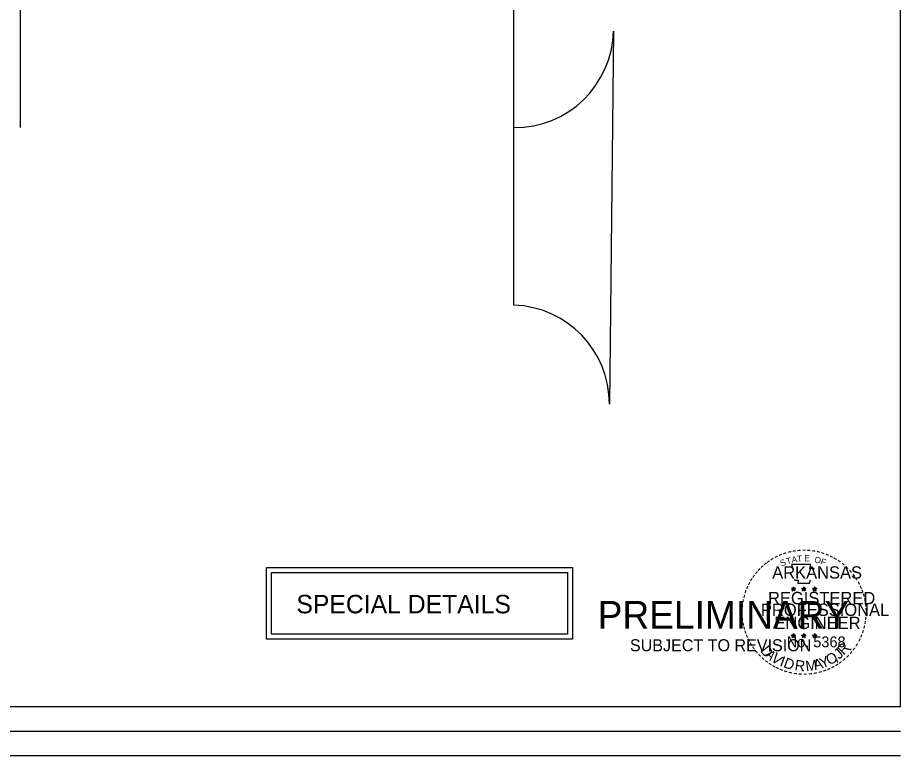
# Model space of a CAD drawing. Extents: x 1944905 to 1956777, y 763871 to 764977.
# Drawn here: x 1950934 to 1951650, y 763871 to 764469 of the extents above; entities that cross this region are included whole.
import ezdxf

# ---------------------------------------------------------------- set-up
doc = ezdxf.new("R2010")
doc.units = 0
for name, color, linetype in [('Default', 7, 'Continuous'), ('R_Border PE', 7, 'Continuous'), ('R_Drive', 7, 'Continuous'), ('R_Horz Alg Annot', 7, 'Continuous')]:
    doc.layers.add(name, color=color, linetype=linetype)

msp = doc.modelspace()

# ---------------------------------------------------------------- linework, layer by layer
at = {"layer": 'Default'}
for p, q in [((1951649.9, 763910.07), (1951649.9, 764937.29)), ((1951649.9, 763910.07), (1950069, 763910.07)), ((1950036.16, 763890.36), (1951649.9, 763890.36)), ((1950036.16, 763870.67), (1951649.9, 763870.67))]:
    msp.add_line(p, q, dxfattribs=at)
for points in [[(1951136, 764022.9), (1951384.01, 764022.9), (1951384.01, 763964.87), (1951136, 763964.87)], [(1951140, 764018.9), (1951380.01, 764018.9), (1951380.01, 763968.87), (1951140, 763968.87)]]:
    msp.add_lwpolyline(points, close=True, dxfattribs=at)
at = {"layer": 'R_Border PE'}
for p, q in [((1951561.56, 764006.04), (1951563.26, 764005.49)), ((1951561.56, 764006.04), (1951562.81, 764005.89)), ((1951561.56, 764006.04), (1951562.81, 764005.84)), ((1951561.56, 764006.04), (1951562.76, 764005.74)), ((1951561.56, 764006.04), (1951562.76, 764005.54)), ((1951561.56, 764006.04), (1951562.71, 764005.44)), ((1951561.56, 764006.04), (1951562.71, 764005.34)), ((1951563.26, 764007.29), (1951563.01, 764006.09)), ((1951563.26, 764007.29), (1951563.06, 764006.04)), ((1951563.26, 764007.29), (1951563.21, 764006.04)), ((1951563.26, 764005.49), (1951563.26, 764007.29)), ((1951563.26, 764007.29), (1951563.61, 764006.04)), ((1951563.26, 764007.29), (1951563.51, 764006.04)), ((1951563.26, 764007.29), (1951563.41, 764006.09)), ((1951565.01, 764006.04), (1951563.26, 764005.49)), ((1951565.01, 764006.04), (1951563.51, 764005.94)), ((1951565.01, 764006.04), (1951563.61, 764005.79)), ((1951565.01, 764006.04), (1951563.61, 764005.69)), ((1951565.01, 764006.04), (1951563.91, 764005.59)), ((1951565.01, 764006.04), (1951564.01, 764005.54)), ((1951565.01, 764006.04), (1951564.06, 764005.49)), ((1951569.86, 764006.04), (1951571.61, 764005.49)), ((1951569.86, 764006.04), (1951571.16, 764005.89)), ((1951569.86, 764006.04), (1951571.16, 764005.84)), ((1951569.86, 764006.04), (1951571.11, 764005.74)), ((1951569.86, 764006.04), (1951571.11, 764005.54)), ((1951569.86, 764006.04), (1951571.06, 764005.44)), ((1951569.86, 764006.04), (1951571.06, 764005.34)), ((1951571.61, 764007.29), (1951571.36, 764006.09)), ((1951571.61, 764007.29), (1951571.41, 764006.04)), ((1951571.61, 764007.29), (1951571.56, 764006.04)), ((1951571.61, 764005.49), (1951571.61, 764007.29)), ((1951571.61, 764007.29), (1951571.96, 764006.04)), ((1951571.61, 764007.29), (1951571.86, 764006.04)), ((1951571.61, 764007.29), (1951571.76, 764006.09)), ((1951573.36, 764006.04), (1951571.61, 764005.49)), ((1951573.36, 764006.04), (1951571.81, 764005.94)), ((1951573.36, 764006.04), (1951571.91, 764005.79)), ((1951573.36, 764006.04), (1951571.91, 764005.69)), ((1951573.36, 764006.04), (1951572.26, 764005.59)), ((1951573.36, 764006.04), (1951572.36, 764005.54)), ((1951573.36, 764006.04), (1951572.41, 764005.49)), ((1951578.71, 764005.99), (1951580.46, 764005.44)), ((1951578.71, 764005.99), (1951580.01, 764005.84)), ((1951578.71, 764005.99), (1951580.01, 764005.74)), ((1951578.71, 764005.99), (1951579.96, 764005.64)), ((1951578.71, 764005.99), (1951579.91, 764005.49)), ((1951578.71, 764005.99), (1951579.91, 764005.39)), ((1951578.71, 764005.99), (1951579.91, 764005.29)), ((1951580.46, 764007.24), (1951580.16, 764006.04)), ((1951580.46, 764007.24), (1951580.26, 764005.99)), ((1951580.46, 764007.24), (1951580.36, 764005.99)), ((1951580.46, 764005.44), (1951580.46, 764007.24)), ((1951580.46, 764007.24), (1951580.81, 764005.99)), ((1951580.46, 764007.24), (1951580.71, 764005.99)), ((1951580.46, 764007.24), (1951580.56, 764006.04)), ((1951582.21, 764005.99), (1951580.46, 764005.44)), ((1951582.21, 764005.99), (1951580.66, 764005.89)), ((1951582.21, 764005.99), (1951580.76, 764005.74)), ((1951582.21, 764005.99), (1951580.76, 764005.64)), ((1951582.21, 764005.99), (1951581.11, 764005.54)), ((1951582.21, 764005.99), (1951581.16, 764005.49)), ((1951582.21, 764005.99), (1951581.26, 764005.44)), ((1951562.21, 764003.99), (1951563.26, 764005.49)), ((1951562.21, 764003.99), (1951562.76, 764005.39)), ((1951562.21, 764003.99), (1951562.81, 764005.24)), ((1951562.21, 764003.99), (1951562.91, 764005.19)), ((1951562.21, 764003.99), (1951563.26, 764005.09)), ((1951562.21, 764003.99), (1951563.06, 764005.04)), ((1951562.21, 764003.99), (1951563.31, 764004.94)), ((1951564.36, 764003.99), (1951563.26, 764005.49)), ((1951564.36, 764003.99), (1951563.26, 764005.09)), ((1951564.36, 764003.99), (1951563.26, 764004.94)), ((1951564.36, 764003.99), (1951563.46, 764005.04)), ((1951564.36, 764003.99), (1951563.61, 764005.24)), ((1951564.36, 764003.99), (1951563.66, 764005.44)), ((1951564.36, 764003.99), (1951563.76, 764005.44)), ((1951570.56, 764003.99), (1951571.61, 764005.49)), ((1951570.56, 764003.99), (1951571.11, 764005.39)), ((1951570.56, 764003.99), (1951571.16, 764005.24)), ((1951570.56, 764003.99), (1951571.26, 764005.19)), ((1951570.56, 764003.99), (1951571.61, 764005.09)), ((1951570.56, 764003.99), (1951571.41, 764005.04)), ((1951570.56, 764003.99), (1951571.66, 764004.94)), ((1951572.71, 764003.99), (1951571.61, 764005.49)), ((1951572.71, 764003.99), (1951571.61, 764005.09)), ((1951572.71, 764003.99), (1951571.61, 764004.94)), ((1951572.71, 764003.99), (1951571.81, 764005.04)), ((1951572.71, 764003.99), (1951571.96, 764005.24)), ((1951572.71, 764003.99), (1951572.01, 764005.44)), ((1951572.71, 764003.99), (1951572.11, 764005.44)), ((1951579.41, 764003.94), (1951580.46, 764005.44)), ((1951579.41, 764003.94), (1951579.96, 764005.34)), ((1951579.41, 764003.94), (1951580.01, 764005.14)), ((1951579.41, 764003.94), (1951580.11, 764005.14)), ((1951579.41, 764003.94), (1951580.46, 764005.04)), ((1951579.41, 764003.94), (1951580.26, 764004.99)), ((1951579.41, 764003.94), (1951580.51, 764004.89)), ((1951581.51, 764003.94), (1951580.46, 764005.44)), ((1951581.51, 764003.94), (1951580.46, 764005.04)), ((1951581.51, 764003.94), (1951580.46, 764004.89)), ((1951581.51, 764003.94), (1951580.66, 764004.99)), ((1951581.51, 764003.94), (1951580.81, 764005.19)), ((1951581.51, 764003.94), (1951580.86, 764005.39)), ((1951581.51, 764003.94), (1951580.96, 764005.39)), ((1951561.51, 763968.19), (1951563.26, 763967.64)), ((1951561.51, 763968.19), (1951562.81, 763968.04)), ((1951561.51, 763968.19), (1951562.81, 763967.94)), ((1951561.51, 763968.19), (1951562.76, 763967.84)), ((1951561.51, 763968.19), (1951562.71, 763967.69)), ((1951561.51, 763968.19), (1951562.71, 763967.59)), ((1951561.51, 763968.19), (1951562.71, 763967.44)), ((1951562.21, 763966.14), (1951563.26, 763967.64)), ((1951562.21, 763966.14), (1951562.76, 763967.54)), ((1951562.21, 763966.14), (1951562.81, 763967.34)), ((1951562.21, 763966.14), (1951562.91, 763967.29)), ((1951562.21, 763966.14), (1951563.26, 763967.24)), ((1951562.21, 763966.14), (1951563.06, 763967.19)), ((1951562.21, 763966.14), (1951563.31, 763967.09)), ((1951563.26, 763969.44), (1951562.96, 763968.24)), ((1951563.26, 763969.44), (1951563.06, 763968.19)), ((1951563.26, 763969.44), (1951563.16, 763968.19)), ((1951563.26, 763967.64), (1951563.26, 763969.44)), ((1951563.26, 763969.44), (1951563.61, 763968.19)), ((1951563.26, 763969.44), (1951563.51, 763968.19)), ((1951563.26, 763969.44), (1951563.36, 763968.19)), ((1951565.01, 763968.19), (1951563.26, 763967.64)), ((1951564.31, 763966.14), (1951563.26, 763967.64)), ((1951564.31, 763966.14), (1951563.26, 763967.19)), ((1951564.31, 763966.14), (1951563.26, 763967.09)), ((1951565.01, 763968.19), (1951563.46, 763968.09)), ((1951564.31, 763966.14), (1951563.46, 763967.19)), ((1951565.01, 763968.19), (1951563.56, 763967.94)), ((1951565.01, 763968.19), (1951563.56, 763967.84)), ((1951564.31, 763966.14), (1951563.61, 763967.34)), ((1951564.31, 763966.14), (1951563.66, 763967.59)), ((1951564.31, 763966.14), (1951563.76, 763967.59)), ((1951565.01, 763968.19), (1951563.91, 763967.74)), ((1951565.01, 763968.19), (1951563.96, 763967.69)), ((1951565.01, 763968.19), (1951564.06, 763967.59)), ((1951569.86, 763968.19), (1951571.61, 763967.64)), ((1951569.86, 763968.19), (1951571.16, 763968.04)), ((1951569.86, 763968.19), (1951571.11, 763967.94)), ((1951569.86, 763968.19), (1951571.11, 763967.84)), ((1951569.86, 763968.19), (1951571.06, 763967.69)), ((1951569.86, 763968.19), (1951571.06, 763967.59)), ((1951569.86, 763968.19), (1951571.06, 763967.44)), ((1951570.51, 763966.14), (1951571.61, 763967.64)), ((1951570.51, 763966.14), (1951571.11, 763967.54)), ((1951570.51, 763966.14), (1951571.16, 763967.34)), ((1951570.51, 763966.14), (1951571.26, 763967.29)), ((1951570.51, 763966.14), (1951571.61, 763967.24)), ((1951570.51, 763966.14), (1951571.41, 763967.19)), ((1951570.51, 763966.14), (1951571.61, 763967.09)), ((1951571.61, 763969.44), (1951571.31, 763968.24)), ((1951571.61, 763969.44), (1951571.41, 763968.19)), ((1951571.61, 763969.44), (1951571.51, 763968.19)), ((1951571.61, 763967.64), (1951571.61, 763969.44)), ((1951571.61, 763969.44), (1951571.96, 763968.19)), ((1951571.61, 763969.44), (1951571.86, 763968.19)), ((1951571.61, 763969.44), (1951571.71, 763968.19)), ((1951573.36, 763968.19), (1951571.61, 763967.64)), ((1951572.66, 763966.14), (1951571.61, 763967.64)), ((1951572.66, 763966.14), (1951571.61, 763967.19)), ((1951572.66, 763966.14), (1951571.61, 763967.09)), ((1951573.36, 763968.19), (1951571.81, 763968.09)), ((1951572.66, 763966.14), (1951571.81, 763967.19)), ((1951573.36, 763968.19), (1951571.91, 763967.94)), ((1951573.36, 763968.19), (1951571.91, 763967.84)), ((1951572.66, 763966.14), (1951571.96, 763967.34)), ((1951572.66, 763966.14), (1951572.01, 763967.59)), ((1951572.66, 763966.14), (1951572.11, 763967.59)), ((1951573.36, 763968.19), (1951572.21, 763967.74)), ((1951573.36, 763968.19), (1951572.31, 763967.69)), ((1951573.36, 763968.19), (1951572.41, 763967.59)), ((1951578.71, 763968.14), (1951580.46, 763967.54)), ((1951578.71, 763968.14), (1951579.96, 763967.99)), ((1951578.71, 763968.14), (1951579.96, 763967.89)), ((1951578.71, 763968.14), (1951579.91, 763967.79)), ((1951578.71, 763968.14), (1951579.91, 763967.64)), ((1951578.71, 763968.14), (1951579.86, 763967.49)), ((1951578.71, 763968.14), (1951579.86, 763967.39)), ((1951579.36, 763966.09), (1951580.46, 763967.54)), ((1951579.36, 763966.09), (1951579.91, 763967.44)), ((1951579.36, 763966.09), (1951580.01, 763967.29)), ((1951579.36, 763966.09), (1951580.11, 763967.24)), ((1951579.36, 763966.09), (1951580.26, 763967.14)), ((1951579.36, 763966.09), (1951580.41, 763967.14)), ((1951579.36, 763966.09), (1951580.46, 763967.04)), ((1951580.46, 763969.39), (1951580.16, 763968.14)), ((1951580.46, 763969.39), (1951580.26, 763968.14)), ((1951580.46, 763969.39), (1951580.36, 763968.14)), ((1951581.51, 763966.09), (1951580.41, 763967.14)), ((1951581.51, 763966.09), (1951580.41, 763966.99)), ((1951580.46, 763967.54), (1951580.46, 763969.39)), ((1951580.46, 763969.39), (1951580.76, 763968.14)), ((1951580.46, 763969.39), (1951580.71, 763968.14)), ((1951580.46, 763969.39), (1951580.56, 763968.14)), ((1951582.16, 763968.14), (1951580.46, 763967.54)), ((1951581.51, 763966.09), (1951580.46, 763967.54)), ((1951581.51, 763966.09), (1951580.61, 763967.14)), ((1951582.16, 763968.14), (1951580.66, 763967.99)), ((1951582.16, 763968.14), (1951580.76, 763967.89)), ((1951582.16, 763968.14), (1951580.76, 763967.79)), ((1951581.51, 763966.09), (1951580.81, 763967.54)), ((1951581.51, 763966.09), (1951580.81, 763967.29)), ((1951581.51, 763966.09), (1951580.96, 763967.54)), ((1951582.16, 763968.14), (1951581.06, 763967.64)), ((1951582.16, 763968.14), (1951581.16, 763967.59)), ((1951582.16, 763968.14), (1951581.21, 763967.54))]:
    msp.add_line(p, q, dxfattribs=at)
for points in [[(1951561.76, 764025.44), (1951563.11, 764021.29)], [(1951579.31, 764020.84), (1951580.01, 764022.24), (1951576.56, 764022.14), (1951577.31, 764025.44), (1951561.76, 764025.44)], [(1951564.21, 764013.34), (1951564.21, 764012.89), (1951567.01, 764012.79), (1951566.76, 764010.44), (1951576.11, 764010.44), (1951577.11, 764013.09)], [(1951563.26, 764007.29), (1951564.36, 764003.99), (1951561.56, 764006.04), (1951565.01, 764006.04), (1951562.21, 764003.99), (1951563.26, 764007.29)], [(1951571.61, 764007.29), (1951572.71, 764003.99), (1951569.86, 764006.04), (1951573.36, 764006.04), (1951570.56, 764003.99), (1951571.61, 764007.29)], [(1951580.46, 764007.24), (1951581.51, 764003.94), (1951578.71, 764005.99), (1951582.21, 764005.99), (1951579.41, 764003.94), (1951580.46, 764007.24)], [(1951563.26, 763969.44), (1951564.31, 763966.14), (1951561.51, 763968.19), (1951565.01, 763968.19), (1951562.21, 763966.14), (1951563.26, 763969.44)], [(1951571.61, 763969.44), (1951572.66, 763966.14), (1951569.86, 763968.19), (1951573.36, 763968.19), (1951570.51, 763966.14), (1951571.61, 763969.44)], [(1951580.46, 763969.39), (1951581.51, 763966.09), (1951578.71, 763968.14), (1951582.16, 763968.14), (1951579.36, 763966.09), (1951580.46, 763969.39)]]:
    msp.add_lwpolyline(points, dxfattribs=at)
for centre, radius in [((1951563.27, 764005.49), 0.861), ((1951563.27, 764005.49), 0.78), ((1951563.27, 764005.49), 0.723), ((1951563.27, 764005.49), 0.664), ((1951563.27, 764005.49), 0.579), ((1951563.27, 764005.49), 0.537), ((1951563.27, 764005.49), 0.495), ((1951571.61, 764005.49), 0.861), ((1951571.61, 764005.49), 0.78), ((1951571.61, 764005.49), 0.723), ((1951571.61, 764005.49), 0.664), ((1951571.61, 764005.49), 0.579), ((1951571.61, 764005.49), 0.537), ((1951571.61, 764005.49), 0.495), ((1951580.45, 764005.43), 0.861), ((1951580.45, 764005.43), 0.78), ((1951580.45, 764005.43), 0.723), ((1951580.45, 764005.43), 0.664), ((1951580.45, 764005.43), 0.579), ((1951563.27, 764005.49), 0.426), ((1951563.27, 764005.49), 0.374), ((1951563.27, 764005.49), 0.311), ((1951563.27, 764005.49), 0.248), ((1951563.27, 764005.49), 0.185), ((1951563.27, 764005.49), 0.148), ((1951563.27, 764005.49), 0.0721), ((1951571.61, 764005.49), 0.426), ((1951571.61, 764005.49), 0.374), ((1951571.61, 764005.49), 0.311), ((1951571.61, 764005.49), 0.248), ((1951571.61, 764005.49), 0.185), ((1951571.61, 764005.49), 0.148), ((1951571.61, 764005.49), 0.0721), ((1951580.45, 764005.43), 0.537), ((1951580.45, 764005.43), 0.495), ((1951580.45, 764005.43), 0.426), ((1951580.45, 764005.43), 0.374), ((1951580.45, 764005.43), 0.311), ((1951580.45, 764005.43), 0.248), ((1951580.45, 764005.43), 0.185), ((1951580.45, 764005.43), 0.148), ((1951580.45, 764005.43), 0.0721), ((1951563.25, 763967.63), 0.861), ((1951563.25, 763967.63), 0.78), ((1951563.25, 763967.63), 0.723), ((1951563.25, 763967.63), 0.664), ((1951563.25, 763967.63), 0.579), ((1951563.25, 763967.63), 0.537), ((1951563.25, 763967.63), 0.495), ((1951563.25, 763967.63), 0.426), ((1951563.25, 763967.63), 0.374), ((1951563.25, 763967.63), 0.311), ((1951563.25, 763967.63), 0.248), ((1951563.25, 763967.63), 0.185), ((1951563.25, 763967.63), 0.148), ((1951563.25, 763967.63), 0.0721), ((1951571.59, 763967.63), 0.861), ((1951571.59, 763967.63), 0.78), ((1951571.59, 763967.63), 0.723), ((1951571.59, 763967.63), 0.664), ((1951571.59, 763967.63), 0.579), ((1951571.59, 763967.63), 0.537), ((1951571.59, 763967.63), 0.495), ((1951571.59, 763967.63), 0.426), ((1951571.59, 763967.63), 0.374), ((1951571.59, 763967.63), 0.311), ((1951571.59, 763967.63), 0.248), ((1951571.59, 763967.63), 0.185), ((1951571.59, 763967.63), 0.148), ((1951571.59, 763967.63), 0.0721), ((1951580.43, 763967.57), 0.861), ((1951580.43, 763967.57), 0.78), ((1951580.43, 763967.57), 0.723), ((1951580.43, 763967.57), 0.664), ((1951580.43, 763967.57), 0.579), ((1951580.43, 763967.57), 0.537), ((1951580.43, 763967.57), 0.495), ((1951580.43, 763967.57), 0.426), ((1951580.43, 763967.57), 0.374), ((1951580.43, 763967.57), 0.311), ((1951580.43, 763967.57), 0.248), ((1951580.43, 763967.57), 0.185), ((1951580.43, 763967.57), 0.148), ((1951580.43, 763967.57), 0.0721)]:
    msp.add_circle(centre, radius, dxfattribs=at)
at = {"layer": 'R_Drive'}
for p, q in [((1951417.27, 764457.94), (1951413.99, 764155.56)), ((1951336.5, 764235.83), (1951336.5, 764379.83))]:
    msp.add_line(p, q, dxfattribs=at)
for centre, start, end in [((1951337.29, 764459.82), 269.43122, 358.65108), ((1951333.99, 764155.87), 359.77958, 88.20531)]:
    msp.add_arc(centre, 80, start, end, dxfattribs=at)
at = {"layer": 'R_Horz Alg Annot'}
for points in [[(1950936.5, 764379.83), (1950936.5, 764731.83)], [(1951336.5, 764379.83), (1951336.5, 764731.83)]]:
    msp.add_lwpolyline(points, dxfattribs=at)

# ---------------------------------------------------------------- texts
at = {"layer": 'Default'}
for s, height, p in [('SPECIAL DETAILS', 15, (1951160.19, 763985.86)), ('PRELIMINARY', 22.5, (1951404.5, 763973.37)), ('        SUBJECT TO REVISION', 9.75, (1951401.68, 763955.1))]:
    msp.add_text(s, height=height, dxfattribs=at).set_placement(p)
at = {"layer": 'R_Border PE'}
for s, height, rotation, p in [('-', 8, 19.17608, (1951555.46, 764031.09)), ('-', 8, 13.63015, (1951559.21, 764032.29)), ('-', 8, 10.21935, (1951562.61, 764033.09)), ('-', 8, 5.89682, (1951566.26, 764033.64)), ('-', 8, 0.18623, (1951570.11, 764033.99)), ('-', 8, 357.74304, (1951573.76, 764033.94)), ('-', 8, 352.16173, (1951577.46, 764033.64)), ('-', 8, 347.20489, (1951581.06, 764033.09)), ('-', 8, 342.3362, (1951584.21, 764032.29)), ('-', 8, 36.23174, (1951543.26, 764024.29)), ('-', 8, 34.06357, (1951546.16, 764026.29)), ('-', 8, 28.79182, (1951549.16, 764028.14)), ('-', 8, 24.30721, (1951552.31, 764029.74)), ('S', 5, 21.59401, (1951553.51, 764023.84)), ('T', 5, 16.4036, (1951558.11, 764025.49)), ('A', 5, 11.21318, (1951562.21, 764026.74)), ('T', 5, 6.02276, (1951566.46, 764027.54)), ('E', 5, 0.83234, (1951572.01, 764028.09)), ('O', 5, 350.4515, (1951580.01, 764027.04)), ('F', 5, 340.07066, (1951584.76, 764025.94)), ('-', 8, 337.85509, (1951587.91, 764031.19)), ('-', 8, 334.12109, (1951591.06, 764029.84)), ('-', 8, 329.64089, (1951593.96, 764028.44)), ('-', 8, 325.86266, (1951597.16, 764026.59)), ('-', 8, 48.42305, (1951536.51, 764017.94)), ('-', 8, 42.96224, (1951538.71, 764020.34)), ('-', 8, 38.95066, (1951540.91, 764022.44)), ('-', 8, 320.52971, (1951600.21, 764024.49)), ('-', 8, 315.57859, (1951603.21, 764022.04)), ('-', 8, 309.87973, (1951606.06, 764019.29)), ('-', 8, 58.07063, (1951530.76, 764010.04)), ('-', 8, 54.23247, (1951532.41, 764012.69)), ('-', 8, 50.61417, (1951534.46, 764015.54)), ('-', 8, 306.65218, (1951608.71, 764016.29)), ('-', 7, 303.67529, (1951611.11, 764013.44)), ('-', 8, 67.77427, (1951527.91, 764003.94)), ('-', 8, 62.87135, (1951529.21, 764006.99)), ('-', 8, 299.66835, (1951612.71, 764010.39)), ('-', 8, 294.66279, (1951614.31, 764007.34)), ('-', 8, 75.46096, (1951525.86, 763997.19)), ('-', 8, 72.39447, (1951526.81, 764000.79)), ('-', 8, 290.57283, (1951615.61, 764004.44)), ('-', 8, 285.12326, (1951616.81, 764001.54)), ('-', 8, 85.18634, (1951524.81, 763990.19)), ('-', 8, 81.20126, (1951525.16, 763993.64)), ('-', 8, 280.54934, (1951617.81, 763997.84)), ('-', 8, 276.59616, (1951618.61, 763993.99)), ('-', 8, 94.19588, (1951524.86, 763983.04)), ('-', 8, 89.06224, (1951524.66, 763986.69)), ('-', 8, 274.33011, (1951618.91, 763990.39)), ('-', 8, 269.94067, (1951619.06, 763987.24)), ('-', 8, 98.94793, (1951525.21, 763979.74)), ('-', 8, 101.71495, (1951525.91, 763976.04)), ('-', 8, 260.99529, (1951618.61, 763980.64)), ('-', 8, 263.5172, (1951618.96, 763983.89)), ('-', 8, 105.45785, (1951526.71, 763973.09)), ('-', 8, 109.08742, (1951527.76, 763969.94)), ('-', 8, 252.86809, (1951617.16, 763973.64)), ('-', 8, 255.7626, (1951618.06, 763977.24)), ('-', 8, 114.06432, (1951529.06, 763966.94)), ('-', 8, 115.72885, (1951530.56, 763963.84)), ('-', 8, 244.61971, (1951614.76, 763967.14)), ('-', 8, 247.88866, (1951616.06, 763970.29)), ('-', 8, 120.44712, (1951532.36, 763960.94)), ('-', 8, 125.89344, (1951534.36, 763958.14)), ('-', 8, 130.71812, (1951536.66, 763955.34)), ('D', 8.47, 308.02669, (1951535.91, 763955.44)), ('J', 8.47, 40.15065, (1951600.26, 763948.09)), ('R', 8.47, 46.29225, (1951604.01, 763951.44)), ('-', 8, 233.84524, (1951610.76, 763960.14)), ('-', 8, 239.07125, (1951612.76, 763963.39)), ('-', 8, 134.22381, (1951539.26, 763952.64)), ('-', 8, 138.93382, (1951541.91, 763950.29)), ('A', 7.7, 314.16829, (1951539.66, 763951.99)), ('V', 8.47, 322.07513, (1951544.31, 763947.94)), ('ID', 8.47, 339.24466, (1951551.56, 763943.49)), ('A', 8.47, 15.04444, (1951580.56, 763939.74)), ('Y', 8.47, 21.72586, (1951586.36, 763941.09)), ('O', 8.47, 27.86746, (1951592.26, 763943.49)), ('-', 8, 221.08509, (1951603.61, 763951.94)), ('-', 8, 225.76533, (1951606.21, 763954.49)), ('-', 8, 231.25377, (1951608.61, 763957.29)), ('-', 8, 144.64634, (1951544.66, 763948.29)), ('-', 8, 148.08978, (1951547.46, 763946.44)), ('-', 8, 151.57039, (1951550.36, 763944.79)), ('-', 8, 154.60019, (1951552.96, 763943.59)), ('R', 8.47, 351.48461, (1951563.86, 763939.94)), ('M', 8.47, 7.38422, (1951573.56, 763938.79)), ('-', 8, 204.25161, (1951592.26, 763944.29)), ('-', 8, 207.35684, (1951595.41, 763945.89)), ('-', 8, 212.24909, (1951598.21, 763947.64)), (',', 8.45, 13.66842, (1951597.11, 763946.74)), ('-', 8, 215.73633, (1951600.86, 763949.54)), ('-', 8, 158.56121, (1951556.11, 763942.29)), ('-', 8, 162.79826, (1951559.51, 763941.24)), ('-', 8, 167.55551, (1951563.11, 763940.39)), ('-', 8, 173.11546, (1951566.96, 763939.84)), ('-', 8, 176.51827, (1951570.71, 763939.59)), ('.', 7.7, 351.01787, (1951569.66, 763938.99)), ('-', 8, 181.59176, (1951574.41, 763939.69)), ('-', 8, 185.81666, (1951578.46, 763940.09)), ('-', 8, 191.28576, (1951582.16, 763940.74)), ('-', 8, 195.47429, (1951585.81, 763941.74)), ('-', 8, 200.71842, (1951589.16, 763942.94))]:
    msp.add_text(s, height=height, rotation=rotation, dxfattribs=at).set_placement(p)
for s, height, p in [('ARKANSAS', 10, (1951546.01, 764013.99)), ('REGISTERED', 10, (1951542.61, 763993.24)), ('PROFESSIONAL', 9.9999, (1951536.86, 763983.74)), ('ENGINEER', 10, (1951547.81, 763973.09)), ('No. 5368', 8.785, (1951557.81, 763958.34)), ('.', 8.45, (1951608.06, 763955.84))]:
    msp.add_text(s, height=height, dxfattribs=at).set_placement(p)

doc.saveas('drawing.dxf')
